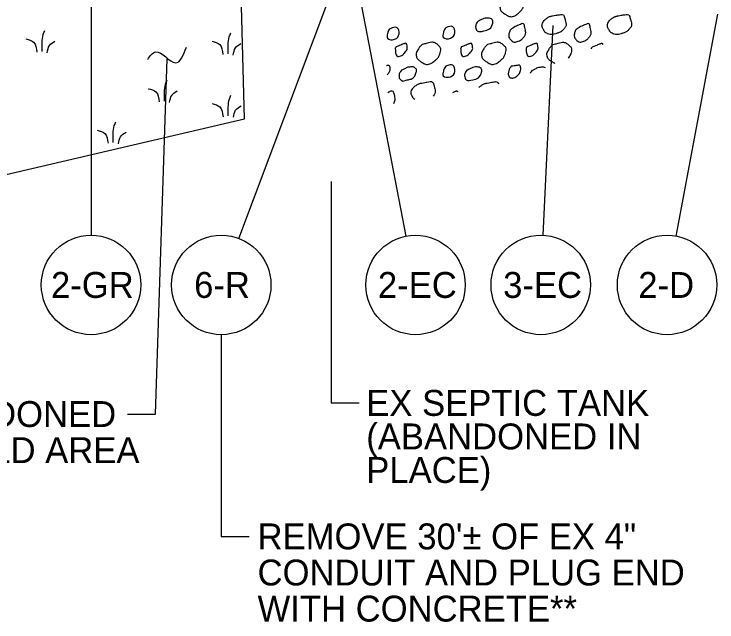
# Model space of a CAD drawing. Extents: x 0 to 3369, y -440 to 440.
# Drawn here: x 466.9 to 542.9, y 205.3 to 270.9 of the extents above; entities that cross this region are included whole.
import ezdxf

# ---------------------------------------------------------------- set-up
doc = ezdxf.new("R2010")
doc.units = 0
for name, color, linetype in [('GE_P_Alignment', 7, 'Continuous'), ('GE_P_Alignment_100_Stations', 7, 'Continuous'), ('PF_P_Grade_Line', 7, 'Continuous'), ('PV_P_EOP', 7, 'Continuous')]:
    doc.layers.add(name, color=color, linetype=linetype)

msp = doc.modelspace()

# ---------------------------------------------------------------- linework, layer by layer
at = {"layer": 'GE_P_Alignment'}
for points in [[(520.025, 272.807), (520.262, 272.871), (520.5, 272.933), (520.737, 272.994), (521.083, 273.084), (521.432, 273.02), (521.779, 272.731), (522.047, 272.506), (522.065, 272.174), (521.994, 271.926), (521.904, 271.612), (521.706, 271.315), (521.402, 271.056), (521.022, 270.731), (520.494, 270.604), (520.105, 270.834), (519.79, 271.021), (519.458, 271.301), (519.397, 271.631), (519.359, 271.837), (519.466, 272.076), (519.587, 272.267), (519.673, 272.404), (519.75, 272.543), (519.864, 272.652), (519.917, 272.704), (519.971, 272.756), (520.025, 272.807)], [(525.068, 270.747), (525.371, 270.799), (525.674, 270.856), (525.977, 270.899), (526.279, 270.941), (526.419, 270.422), (526.495, 270.139), (526.564, 269.881), (526.519, 269.566), (526.302, 269.325), (526.035, 269.03), (525.739, 268.917), (525.41, 268.82), (525.127, 268.737), (524.811, 268.707), (524.53, 268.825), (524.359, 268.897), (524.235, 269.022), (524.132, 269.182), (523.959, 269.45), (523.907, 269.819), (524.058, 270.072), (524.158, 270.24), (524.294, 270.388), (524.468, 270.499), (524.616, 270.593), (524.757, 270.681), (524.92, 270.715), (524.975, 270.727), (525.03, 270.739), (525.085, 270.75)], [(532.14, 270.747), (532.442, 270.799), (532.746, 270.856), (533.048, 270.899), (533.351, 270.941), (533.491, 270.422), (533.567, 270.139), (533.635, 269.881), (533.591, 269.566), (533.373, 269.325), (533.107, 269.03), (532.81, 268.917), (532.482, 268.82), (532.199, 268.737), (531.883, 268.707), (531.602, 268.825), (531.431, 268.897), (531.307, 269.022), (531.203, 269.182), (531.03, 269.45), (530.979, 269.819), (531.13, 270.072), (531.23, 270.24), (531.366, 270.388), (531.54, 270.499), (531.687, 270.593), (531.828, 270.681), (531.992, 270.715), (532.047, 270.727), (532.102, 270.739), (532.157, 270.75)], [(521.028, 269.582), (521.263, 269.683), (521.497, 269.783), (521.732, 269.884), (521.975, 269.988), (522.093, 269.455), (522.147, 269.207), (522.203, 268.945), (522.135, 268.651), (521.923, 268.397), (521.724, 268.158), (521.496, 268.044), (521.257, 267.972), (521.065, 267.914), (520.823, 267.905), (520.635, 268.09), (520.407, 268.315), (520.323, 268.58), (520.368, 268.809), (520.405, 268.991), (520.49, 269.23), (520.66, 269.344), (520.783, 269.425), (520.906, 269.502), (521.028, 269.582)], [(528.1, 269.582), (528.334, 269.683), (528.569, 269.783), (528.803, 269.884), (529.046, 269.988), (529.165, 269.455), (529.218, 269.207), (529.275, 268.945), (529.207, 268.651), (528.995, 268.397), (528.796, 268.158), (528.568, 268.044), (528.328, 267.972), (528.136, 267.914), (527.895, 267.905), (527.707, 268.09), (527.479, 268.315), (527.394, 268.58), (527.44, 268.809), (527.476, 268.991), (527.561, 269.23), (527.732, 269.344), (527.854, 269.425), (527.977, 269.502), (528.1, 269.582)], [(508.168, 267.392), (508.485, 267.52), (508.802, 267.656), (509.118, 267.777), (509.274, 267.836), (509.356, 267.489), (509.37, 267.34), (509.389, 267.141), (509.236, 266.933), (509.072, 266.735), (508.849, 266.467), (508.287, 266.272), (508.172, 266.567), (508.11, 266.724), (508.1, 266.885), (508.093, 267.047), (508.09, 267.127), (508.06, 267.217), (508.102, 267.289), (508.123, 267.325), (508.146, 267.357), (508.168, 267.392)], [(510.967, 267.644), (511.204, 267.707), (511.441, 267.769), (511.678, 267.83), (512.025, 267.92), (512.373, 267.857), (512.72, 267.567), (512.989, 267.342), (513.006, 267.01), (512.935, 266.762), (512.845, 266.449), (512.647, 266.151), (512.343, 265.892), (511.963, 265.567), (511.435, 265.44), (511.047, 265.67), (510.732, 265.857), (510.399, 266.137), (510.338, 266.467), (510.3, 266.673), (510.407, 266.912), (510.528, 267.104), (510.615, 267.24), (510.691, 267.379), (510.805, 267.489), (510.859, 267.541), (510.912, 267.592), (510.967, 267.644)], [(515.24, 267.392), (515.557, 267.52), (515.873, 267.656), (516.19, 267.777), (516.346, 267.836), (516.428, 267.489), (516.442, 267.34), (516.46, 267.141), (516.308, 266.933), (516.143, 266.735), (515.92, 266.467), (515.359, 266.272), (515.243, 266.567), (515.182, 266.724), (515.171, 266.885), (515.165, 267.047), (515.162, 267.127), (515.131, 267.217), (515.173, 267.289), (515.194, 267.325), (515.218, 267.357), (515.24, 267.392)], [(518.038, 267.644), (518.275, 267.707), (518.513, 267.769), (518.75, 267.83), (519.096, 267.92), (519.445, 267.857), (519.792, 267.567), (520.06, 267.342), (520.078, 267.01), (520.007, 266.762), (519.917, 266.449), (519.719, 266.151), (519.415, 265.892), (519.035, 265.567), (518.507, 265.44), (518.118, 265.67), (517.803, 265.857), (517.471, 266.137), (517.41, 266.467), (517.372, 266.673), (517.479, 266.912), (517.6, 267.104), (517.686, 267.24), (517.763, 267.379), (517.877, 267.489), (517.93, 267.541), (517.984, 267.592), (518.038, 267.644)], [(522.312, 267.392), (522.628, 267.52), (522.945, 267.656), (523.262, 267.777), (523.417, 267.836), (523.499, 267.489), (523.513, 267.34), (523.532, 267.141), (523.379, 266.933), (523.215, 266.735), (522.992, 266.467), (522.431, 266.272), (522.315, 266.567), (522.253, 266.724), (522.243, 266.885), (522.237, 267.047), (522.233, 267.127), (522.203, 267.217), (522.245, 267.289), (522.266, 267.325), (522.29, 267.357), (522.312, 267.392)], [(525.342, 265.6), (525.29, 265.618), (525.239, 265.641), (525.19, 265.67), (524.875, 265.857), (524.542, 266.137), (524.482, 266.467), (524.444, 266.673), (524.551, 266.912), (524.672, 267.104), (524.758, 267.24), (524.834, 267.379), (524.948, 267.489), (525.002, 267.541), (525.056, 267.592), (525.11, 267.644)], [(525.11, 267.644), (525.347, 267.707), (525.584, 267.769), (525.822, 267.83), (526.168, 267.92), (526.517, 267.857), (526.863, 267.567), (527.132, 267.342), (527.149, 267.01), (527.078, 266.762), (527.018, 266.552), (526.909, 266.349), (526.752, 266.16)], [(529.383, 267.392), (529.7, 267.52), (530.017, 267.656), (530.333, 267.777), (530.407, 267.805), (530.465, 267.741), (530.506, 267.65)], [(529.296, 267.169), (529.293, 267.211), (529.295, 267.252), (529.317, 267.289), (529.338, 267.325), (529.361, 267.357), (529.383, 267.392)], [(507.144, 265.396), (507.176, 265.401), (507.208, 265.405), (507.24, 265.409), (507.467, 265.44), (507.52, 264.949), (507.448, 264.753), (507.399, 264.617), (507.302, 264.481), (507.187, 264.36)], [(508.752, 264.864), (508.918, 264.948), (509.085, 265.031), (509.252, 265.114), (509.435, 265.205), (509.654, 265.224), (509.853, 265.229), (510, 265.234), (510.142, 265.199), (510.275, 265.068), (510.396, 264.948), (510.379, 264.787), (510.343, 264.661), (510.284, 264.451), (510.206, 264.237), (510.002, 264.068), (509.802, 263.901), (509.59, 263.878), (509.375, 263.828), (509.15, 263.775), (508.892, 263.642), (508.672, 263.839), (508.526, 263.97), (508.496, 264.122), (508.5, 264.271), (508.503, 264.403), (508.52, 264.56), (508.603, 264.671), (508.653, 264.736), (508.702, 264.8), (508.752, 264.864)], [(520.62, 265.298), (520.874, 265.334), (521.129, 265.375), (521.383, 265.409), (521.61, 265.44), (521.663, 264.949), (521.592, 264.753), (521.513, 264.536), (521.315, 264.32), (521.112, 264.164), (520.902, 264.004), (520.46, 264.03), (520.338, 264.278), (520.262, 264.433), (520.3, 264.613), (520.343, 264.769), (520.374, 264.879), (520.388, 265.005), (520.46, 265.096), (520.513, 265.163), (520.567, 265.231), (520.62, 265.298)], [(522.895, 264.864), (523.061, 264.948), (523.228, 265.031), (523.395, 265.114), (523.578, 265.205), (523.797, 265.224), (523.997, 265.229), (524.091, 265.232), (524.182, 265.219), (524.271, 265.175)], [(522.682, 264.544), (522.697, 264.59), (522.718, 264.633), (522.747, 264.671), (522.796, 264.736), (522.845, 264.8), (522.895, 264.864)], [(510.181, 261.693), (510.108, 261.756), (510.045, 261.833), (509.988, 261.921), (509.815, 262.189), (509.764, 262.558), (509.915, 262.811), (510.015, 262.979), (510.151, 263.127), (510.325, 263.238), (510.472, 263.332), (510.613, 263.42), (510.777, 263.454), (510.832, 263.466), (510.887, 263.478), (510.942, 263.489)], [(510.925, 263.486), (511.228, 263.538), (511.531, 263.595), (511.833, 263.638), (512.136, 263.68), (512.276, 263.161), (512.352, 262.878), (512.42, 262.62), (512.376, 262.306), (512.159, 262.065)], [(517.121, 262.998), (517.199, 263.089), (517.291, 263.17), (517.397, 263.238), (517.544, 263.332), (517.685, 263.42), (517.848, 263.454), (517.903, 263.466), (517.958, 263.478), (518.013, 263.489)], [(517.997, 263.486), (518.299, 263.538), (518.602, 263.595), (518.905, 263.638), (519.051, 263.658), (519.159, 263.548), (519.24, 263.397)], [(507.265, 262.484), (507.373, 262.53), (507.48, 262.576), (507.588, 262.623), (507.831, 262.727), (507.95, 262.194), (508.003, 261.946), (508.051, 261.725), (508.01, 261.481), (507.869, 261.258)], [(514.297, 262.467), (514.418, 262.519), (514.539, 262.571), (514.66, 262.623), (514.732, 262.654), (514.794, 262.628), (514.846, 262.57)]]:
    msp.add_open_spline(points, degree=3, dxfattribs=at)
for points in [[(517.019, 270.149), (517.519, 270.399), (518.121, 270.514), (518.542, 270.353), (518.611, 269.946), (518.269, 269.353), (517.642, 269.113), (516.939, 269.124), (516.767, 269.556), (516.871, 269.956), (517.019, 270.149)], [(507.517, 269.357), (508.28, 269.469), (508.488, 268.812), (508.008, 268.224), (507.235, 268.337), (507.24, 268.829), (507.357, 269.156), (507.517, 269.357)], [(513.548, 269.467), (514.312, 269.579), (514.52, 268.922), (514.04, 268.334), (513.267, 268.447), (513.272, 268.939), (513.388, 269.266), (513.548, 269.467)], [(513.548, 265.298), (514.312, 265.409), (514.52, 264.753), (514.04, 264.164), (513.267, 264.278), (513.272, 264.769), (513.388, 265.096), (513.548, 265.298)], [(515.823, 264.864), (516.323, 265.114), (516.925, 265.229), (517.347, 265.068), (517.415, 264.661), (517.073, 264.068), (516.447, 263.828), (515.743, 263.839), (515.572, 264.271), (515.675, 264.671), (515.823, 264.864)]]:
    msp.add_spline(points, degree=3, dxfattribs=at)
at = {"layer": 'GE_P_Alignment_100_Stations'}
msp.add_lwpolyline([(448.999, 249.632), (491.761, 259.625), (491.153, 282.617), (448.315, 274.622)], close=True, dxfattribs=at)
at = {"layer": 'PF_P_Grade_Line'}
for points in [[(469.9, 266.913), (469.9, 267.86), (470.019, 268.748), (470.195, 269.163)], [(468.154, 268.253), (468.982, 267.9), (469.337, 266.833)], [(490.014, 266.66), (490.014, 267.607), (490.132, 268.495), (490.309, 268.91)], [(470.455, 266.77), (470.692, 267.538), (471.282, 268.013)], [(488.267, 268), (489.096, 267.647), (489.451, 266.58)], [(490.569, 266.517), (490.806, 267.285), (491.396, 267.76)], [(483.124, 261.535), (483.124, 262.481), (483.243, 263.37), (483.419, 263.785)], [(481.378, 262.875), (482.206, 262.521), (482.561, 261.455)], [(483.679, 261.391), (483.916, 262.16), (484.506, 262.635)], [(490.022, 259.93), (490.022, 260.877), (490.14, 261.765), (490.317, 262.18)], [(488.275, 261.27), (489.104, 260.917), (489.459, 259.85)], [(490.577, 259.787), (490.814, 260.555), (491.404, 261.03)], [(477.587, 257.062), (477.587, 258.009), (477.705, 258.897), (477.882, 259.312)], [(475.84, 258.402), (476.668, 258.049), (477.023, 256.982)], [(478.142, 256.919), (478.378, 257.687), (478.968, 258.162)]]:
    msp.add_spline(points, degree=3, dxfattribs=at)
at = {"layer": 'PV_P_EOP'}
for p, q in [((475.187, 285.868), (475.187, 247.041)), ((509.251, 246.944), (503.482, 276.905)), ((491.158, 246.697), (500.894, 272.595)), ((538.444, 246.949), (542.935, 270.939)), ((524.062, 247.035), (525.143, 269.693)), ((482.151, 227.718), (483.402, 266.094)), ((501.154, 252.831), (501.154, 228.921)), ((489.268, 236.295), (489.268, 214.494)), ((501.154, 228.921), (504.169, 228.921)), ((479.137, 227.718), (482.151, 227.718)), ((489.268, 214.494), (492.282, 214.494))]:
    msp.add_line(p, q, dxfattribs=at)
for centre in [(475.187, 241.668), (489.268, 241.668), (510.267, 241.668), (523.806, 241.668), (537.456, 241.668)]:
    msp.add_circle(centre, 5.373, dxfattribs=at)
msp.add_spline([(481.313, 266.029), (482.181, 266.857), (484.306, 265.662), (485.497, 267.376)], degree=3, dxfattribs=at)

# ---------------------------------------------------------------- texts
for s, p in [('2-GR', (470.859, 240.268)), ('6-R', (486.331, 240.268)), ('2-EC', (506.199, 240.268)), ('3-EC', (519.738, 240.268)), ('2-D', (534.348, 240.268)), ('EX SEPTIC TANK', (504.938, 227.521)), ('ABANDONED', (454.184, 226.318)), ('(ABANDONED IN', (504.938, 223.897)), ('LEACH FIELD AREA', (445.056, 222.416)), ('PLACE)', (504.938, 220.274)), ('REMOVE 30\'± OF EX 4"', (493.189, 213.094)), ('CONDUIT AND PLUG END', (493.189, 209.192)), ('WITH CONCRETE**', (493.189, 205.29))]:
    msp.add_text(s, height=2.8, dxfattribs=at).set_placement(p)

doc.saveas('drawing.dxf')
